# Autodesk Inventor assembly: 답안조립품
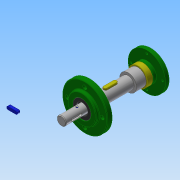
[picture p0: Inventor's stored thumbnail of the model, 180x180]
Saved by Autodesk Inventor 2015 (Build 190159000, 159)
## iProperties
Created: 2017-11
Part Number: 답안조립품
Document SubType Name: Assembly
Designer: user
Author: user
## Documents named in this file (9)
- C:\Users\user\Desktop\471107V1005\답안조립품.iam
- C:\Users\user\Desktop\471107V1005\본체.ipt
- C:\Users\user\Desktop\471107V1005\앞커버.ipt
- C:\Users\user\Desktop\471107V1005\뒤커버.ipt
- C:\Users\user\Desktop\471107V1005\오일 실 15 30 7.ipt
- C:\Users\user\Desktop\471107V1005\베어링 6002.ipt
- C:\Users\user\Desktop\471107V1005\축.ipt
- C:\Users\user\Desktop\471107V1005\키 - 6 x 6 x 22.ipt
- C:\Users\user\Desktop\471107V1005\키 - 5 x 5 x 18.ipt
